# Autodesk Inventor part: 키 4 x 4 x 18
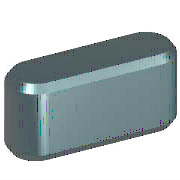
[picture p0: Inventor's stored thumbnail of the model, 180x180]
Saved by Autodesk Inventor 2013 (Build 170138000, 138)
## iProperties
IsCustomPart: 1
Created: 2012-02
Part Number: 키 4 x 4 x 18
Material: 강철, 연강
Description: 키 및 해당 키홈
Document SubType Name: Modeling
Standard: KS B 1311
Designer: mduedu
Standards Organization: KS
Language: ko-KR
Size Designation: 4 x 4 x 18
Categories: <MemberInstance><Categories><Category DisplayName="샤프트 부품" InternalName="7f7aeb1f-a693-4053-b835-cee3144e0d98" Mnemonic="SHFT"><Category DisplayName="키" Interna
Density: 7.86 g/cm^3
Mass: 2.13606 g
Surface Area: 2.87354 cm^2
Volume: 0.271763 cm^3
Author: mduedu
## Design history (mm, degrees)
workplane "Work Plane1"
workplane "Work Plane2"
sketch "스케치1"
  geometry: L1 (2, 2)-(16, 2); L2 (16, -2)-(2, -2); L3 (0, 9.4)-(0, -7.4) reference; L4 (-5, 0)-(30, 0) reference; L5 (18, 0)-(18, 7); A1 r 2 centre (2, 0) between (2, 2) and (2, -2); A2 r 2 centre (16, 0) between (16, -2) and (16, 2)
  constraints: 6 end point, 5 point on circle, 4 tangent, 3 point on line, 2 centre point, 1 horizontal, 1 parallel, 1 perpendicular
  dimensions: "d0" = 2 radius of A1 (= 0.5 x PB); "d13" = 2 radius of A2 (= 0.5 x PB); "d14" = 18 distance between parallel lines of L5 L3 (= NLG)
extrude "본체1" new body sketch "스케치1" taper "d3" = 0 deg; stored distance "d4" = 10
workplane "Work Plane3"
body "Solid1"
chamfer "모따기1" distance "d8" = 0.25 (= PHH); stored, may be unused: second distance "d9" = 0.25 (= PHH), angle "d15" = 45 deg
other parameters: "d1" = -2.5 (= -PNT), "d2" = 1.5 (= PH - PNT), "NLG" = 18 [user parameter; used in 3 equation terms], "PB" = 4 [user parameter; used in 2 equation terms], "PNT" = 2.5 [user parameter; used in 2 equation terms], "PH" = 4 [user parameter; used in 1 equation term], "PHH" = 0.25 [user parameter; used in 2 equation terms], "d10" = 0, "d16" = 0, "d17" = 0, "d18" = 0, "PLB2" = 18 (= NLG) [user parameter], "WDMAX" = 12 [user parameter], "PLB1" = 18 (= NLG) [user parameter], "RR" = 0.08 [user parameter], "PUEB" = 1.8 [user parameter]
